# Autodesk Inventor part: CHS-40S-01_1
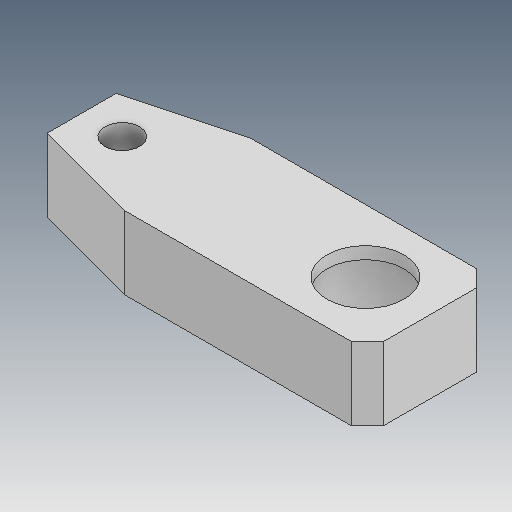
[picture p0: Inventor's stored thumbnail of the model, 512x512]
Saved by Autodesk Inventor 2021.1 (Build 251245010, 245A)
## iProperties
Created: 2019-04
Part Number: CHS-40S-01_1
Material: Ogólny
Document SubType Name: Modeling
Designer: user
Density: 1 g/cm^3
Appearance: Domyślna
Author: user
Revision Number: ÈÎºÎ
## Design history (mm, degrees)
feature "ÊäÈë1"
node "Bryła1"
